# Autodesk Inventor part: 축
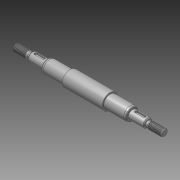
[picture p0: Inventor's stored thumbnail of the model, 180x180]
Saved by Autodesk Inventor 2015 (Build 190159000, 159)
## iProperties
Created: 2015-11
Part Number: 축
Material: 강철, 연강
Document SubType Name: Modeling
Designer: mduedu
Density: 7.86 g/cm^3
Mass: 198.507 g
Surface Area: 75.8873 cm^2
Volume: 25.2553 cm^3
Appearance: 강철
Author: mduedu
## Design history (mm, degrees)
sketch "스케치1"
  geometry: L1 (-86, 0)-(86, 0); L2 (-86, 0)-(-86, 4); L3 (-86, 4)-(-70.732, 4); L4 (-70.732, 4)-(-69, 3); L5 (-69, 3)-(-67, 3); L6 (-67, 3)-(-67, 5); L7 (-67, 5)-(-49, 5); L8 (-49, 5)-(-49, 6.55); L9 (-47.355, 7.5)-(-23, 7.5); L10 (-23, 7.5)-(-23, 9); L11 (0, 0)-(0, 9); L12 (86, 4)-(70.732, 4); L13 (70.732, 4)-(69, 3); L14 (69, 3)-(67, 3); L15 (67, 3)-(67, 5); L16 (67, 5)-(49, 5); L17 (23, 7.5)-(23, 9); L18 (86, 0)-(86, 4); L19 (-23, 9)-(23, 9); L20 (-49, 6.55)-(-47.355, 7.5); L21 (47.355, 7.5)-(23, 7.5); L22 (49, 6.55)-(47.355, 7.5); L23 (49, 5)-(49, 6.55); 1 further point
  constraints: 46 end point, 10 symmetric about line, 6 perpendicular, 5 parallel, 2 midpoint, 1 coincident, 1 horizontal
  dimensions: "d0" = 172 distance of L1.start L1.end (derived); "d1" = 8 diameter of L3 L1; "d2" = 30 deg angle of L4 L5; "d3" = 6 diameter of L5 L1; "d4" = 10 diameter of L7 L1; "d5" = 15 diameter of L9 L1; "d6" = 18 diameter of L19 L1; "d8" = 18 distance of L6.end L7.end; "d9" = 46 distance of L10.end L17.end; "d10" = 2 distance of L4.end L5.end; "d11" = 17 distance from line of L4.end L2; "d16" = 13.1 diameter of L8.end L1; "d17" = 30 deg angle of L20 L9; "d18" = 26 distance between parallel lines of L10 L8
revolve "회전1" sketch "스케치1" stored, may be unused: angle "d12" = 90 deg
chamfer "모따기1" distance "d13" = 1; stored, may be unused: second distance "d14" = 2, angle "d15" = 45 deg
fillet "모깎기1" dims "d19" = 4, "d20" = 0.5
node "작업 평면1"
sketch "스케치2" dims "d23" = 12
  geometry: L1 (-4.5, 1.5)-(4.5, 1.5); L2 (4.5, 1.5)-(4.5, -1.5); L3 (4.5, -1.5)-(-4.5, -1.5); L4 (-4.5, -1.5)-(-4.5, 1.5); L5 (-9, -4)-(-9, 4) reference; 3 further points
  constraints: 8 end point, 2 midpoint, 2 parallel, 2 vertical alignment, 1 horizontal, 1 perpendicular, 4 other
  dimensions: "d21" = 3 distance between parallel lines of L3 L1; "d24" = 3 dimension on L5
extrude "돌출1" cut sketch "스케치2" distance "d25" = 1.8; taper "d26" = 0 deg
feature "스레드1" dims "d27" = 10, "d28" = 0
feature "스레드2" dims "d29" = 10, "d30" = 0
chamfer "모따기2" distance "d31" = 1; stored, may be unused: second distance "d32" = 2, angle "d33" = 45 deg
fillet "모깎기2" dims "d34" = 0.3
node "솔리드1"
mirror "대칭1"
